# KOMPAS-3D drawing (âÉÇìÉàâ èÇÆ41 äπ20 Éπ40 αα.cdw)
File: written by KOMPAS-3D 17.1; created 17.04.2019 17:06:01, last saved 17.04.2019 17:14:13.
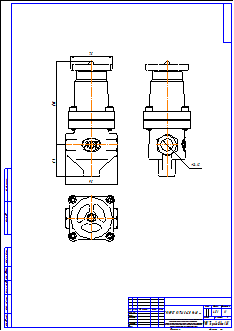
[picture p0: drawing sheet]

Sheet 1: A2, portrait

Title block, sheet 1: name: ГРАНРЕГ КАТ41 Ду20 Ру40 рр; material: Внимание! Данный продукт является объектом авторского права ООО «Торговый Дом АДЛ». / Запрещается изменение, копирование, распространение / (в том числе путем копирования на другие сайты и ресурсы в Интернете) / или любое иное использование информации и объектов без предварительного / согласия правообладателя (ООО «Торговый Дом АДЛ»).; mass: 4,81; sheets: 1; organisation: ООО "Торговый дом АДЛ"; sheet format: A2; stored path: \\adlc.lan\data\АДЛ_ПКД\3D-модели\ADL production\Клапаны КАТ ГРАНРЕГ\КАТ41\KOMPAS 2D\Чертеж.cdw

Views: Спереди 1, Проекционный вид 2, Проекционный вид 3
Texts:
  user
Dimensions and other numbers on the sheet: 95; 57; 150; 75; 24,12; 1:1; 1; 4,81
